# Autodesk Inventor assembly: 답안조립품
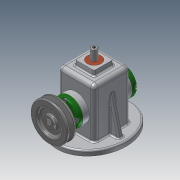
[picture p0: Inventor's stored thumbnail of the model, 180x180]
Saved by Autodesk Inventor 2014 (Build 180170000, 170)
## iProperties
Created: 2017-07
Part Number: 답안조립품
Document SubType Name: Weldment
Designer: user
Weld Material: Welded Aluminum-6061
Author: user
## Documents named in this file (16)
- C:\Users\user\Desktop\470708V1008\답안조립품.iam
- C:\Users\user\Desktop\470708V1008\본체.ipt
- C:\Users\user\Desktop\470708V1008\V벨트풀리.ipt
- C:\Users\user\Desktop\470708V1008\고정핀 1.2 x  8.ipt
- C:\Users\user\Desktop\470708V1008\뒤커버.ipt
- C:\Users\user\Desktop\470708V1008\링크.ipt
- C:\Users\user\Desktop\470708V1008\멈춤나사 M3x8.ipt
- C:\Users\user\Desktop\470708V1008\베어링 12 x 32 x 10.ipt
- C:\Users\user\Desktop\470708V1008\볼트 M4 x 12.ipt
- C:\Users\user\Desktop\470708V1008\부시.ipt
- C:\Users\user\Desktop\470708V1008\슬라이드.ipt
- C:\Users\user\Desktop\470708V1008\앞커버.ipt
- C:\Users\user\Desktop\470708V1008\오일실 12 25 7.ipt
- C:\Users\user\Desktop\470708V1008\키 4 x 4 x 10.ipt
- C:\Users\user\Desktop\470708V1008\편심축.ipt
- C:\Users\user\Desktop\470708V1008\핀 5 x 18.ipt
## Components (3 placed, 3 different names)
1. V벨트풀리:1
2. 핀 5 x 18:1 — 플러쉬:2
3. 고정핀 1.2 x  8:1 — 플러쉬:2
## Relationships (1: Flush 1)
- 플러쉬:2 [Flush]: 핀 5 x 18:1 ↔ 고정핀 1.2 x  8:1
